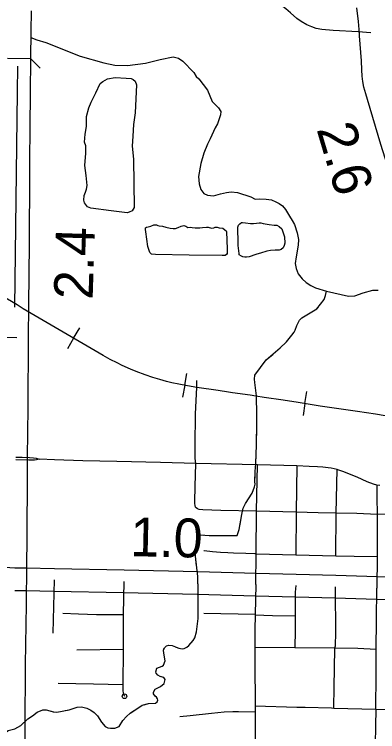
# Model space of a CAD drawing. Extents: x 1382482 to 1385815, y 1168351 to 1170484.
# Drawn here: x 1384330.9 to 1384488.7, y 1168998.2 to 1169309.6 of the extents above; entities that cross this region are included whole.
import ezdxf

# ---------------------------------------------------------------- set-up
doc = ezdxf.new("R2010")
doc.units = 0
for name, color, linetype in [('10', 7, 'Continuous'), ('15', 7, 'Continuous'), ('35', 7, 'Continuous'), ('37', 7, 'Continuous'), ('43', 7, 'Continuous'), ('48', 7, 'Continuous'), ('6', 7, 'Continuous'), ('Default', 7, 'Continuous')]:
    doc.layers.add(name, color=color, linetype=linetype)

msp = doc.modelspace()

# ---------------------------------------------------------------- linework, layer by layer
at = {"layer": '10'}
for points in [[(1384509.13, 1169190.46), (1384507.47, 1169195.39), (1384504.6, 1169205.01), (1384501.25, 1169216.69), (1384497.32, 1169230.02), (1384495.16, 1169236.73), (1384491.99, 1169247.25), (1384490.18, 1169253.06), (1384484.26, 1169272.62), (1384483.6, 1169275.15), (1384482.81, 1169278.01), (1384482.25, 1169280.48), (1384481.95, 1169282.86), (1384481.85, 1169285.5), (1384481.66, 1169289.5), (1384480.92, 1169300.27), (1384480.85, 1169301.27), (1384480.43, 1169306.53), (1384479.68, 1169312.48)], [(1384326.29, 1169069.61), (1384331.5, 1169069.24)], [(1384331.14, 1169069.25), (1384336.01, 1169069.25), (1384348.29, 1169069.04), (1384378.57, 1169068.37), (1384410.62, 1169067.66), (1384436, 1169067.05), (1384453.29, 1169066.56), (1384470.56, 1169066.07), (1384488.49, 1169065.52), (1384517.63, 1169064.98), (1384517.16, 1169063.79), (1384516.67, 1169061.78), (1384516.58, 1169059.48), (1384516.75, 1169057.84), (1384517.21, 1169056.31), (1384517.71, 1169054.98)], [(1384517.71, 1169054.98), (1384488.24, 1169055.52), (1384470.26, 1169056.07), (1384453.01, 1169056.56), (1384435.73, 1169057.05), (1384410.39, 1169057.66), (1384378.35, 1169058.38), (1384348.09, 1169059.04), (1384335.92, 1169059.25), (1384331.15, 1169059.25)]]:
    msp.add_lwpolyline(points, dxfattribs=at)
at = {"layer": '15'}
for points in [[(1384338.14, 1169311.22), (1384338.09, 1169302.22)], [(1384338.09, 1169302.22), (1384337.98, 1169290.5)], [(1384327.98, 1169290.6), (1384337.98, 1169290.5), (1384337.83, 1169275.41), (1384337.65, 1169260.77), (1384337.55, 1169245.45), (1384337.52, 1169235.24), (1384337.47, 1169229.12), (1384337.37, 1169221.35), (1384337.33, 1169210.14), (1384337.09, 1169183.38)], [(1384337.09, 1169183.38), (1384336.96, 1169169.15), (1384336.69, 1169138.8), (1384336.5, 1169117.39), (1384336.5, 1169116.16), (1384336.52, 1169109.18), (1384336.32, 1169082.79), (1384336.16, 1169069.54), (1384336.14, 1169064.2), (1384336.07, 1169059.56), (1384335.99, 1169053.34), (1384335.59, 1169027.3), (1384335.44, 1168999.6), (1384335.28, 1168986.96)]]:
    msp.add_lwpolyline(points, dxfattribs=at)
at = {"layer": '35'}
for points in [[(1384338.06, 1169299.6), (1384340.71, 1169298.59), (1384344.62, 1169297.45), (1384359.5, 1169291.52), (1384369.85, 1169288.51), (1384374.52, 1169287.63), (1384380.02, 1169287.47), (1384387.91, 1169288.44), (1384394.23, 1169290.04), (1384399.97, 1169291.12), (1384402.2, 1169290.62), (1384404.08, 1169289.23), (1384408.82, 1169284.35), (1384409.95, 1169282.6), (1384410.99, 1169281.69), (1384414.89, 1169276.72), (1384416.91, 1169271.73), (1384419.6, 1169269.11), (1384420.56, 1169267.44), (1384420.52, 1169265.95), (1384419.23, 1169262.13), (1384418.21, 1169260.35), (1384416.01, 1169255.62), (1384414.82, 1169253.2), (1384413.28, 1169249.34), (1384411.88, 1169244.82), (1384410.91, 1169239.23), (1384411.18, 1169236), (1384411.94, 1169233.58), (1384413.28, 1169231.91), (1384414.84, 1169231.11), (1384417.37, 1169230.89), (1384420.43, 1169231.65), (1384423.01, 1169232.34), (1384425.11, 1169232.56), (1384427.9, 1169232.24), (1384433.64, 1169230.41), (1384435.52, 1169229.39), (1384437.62, 1169229.49), (1384440.36, 1169229.44), (1384442.67, 1169229.06), (1384444.56, 1169228.26), (1384445.95, 1169227.45), (1384447.35, 1169226.43), (1384448.69, 1169224.92), (1384450.47, 1169221.95), (1384451.65, 1169220.14), (1384452.56, 1169218.4), (1384453.82, 1169214.81)], [(1384372.97, 1169224.31), (1384364.18, 1169225.44), (1384362.67, 1169226.1), (1384361.35, 1169227.8), (1384361.07, 1169228.94), (1384361.25, 1169231.02), (1384361.82, 1169232.44), (1384362.29, 1169233.76), (1384362.58, 1169235.27), (1384362.1, 1169239.71), (1384361.54, 1169243.96), (1384361.63, 1169245.85), (1384362.01, 1169249.26), (1384362.01, 1169252.47), (1384361.44, 1169254.08), (1384361.63, 1169257.57), (1384362.2, 1169260.97), (1384362.29, 1169265.32), (1384363.24, 1169269.01), (1384364.28, 1169271.46), (1384366.26, 1169275.62), (1384368.25, 1169279.59), (1384369.38, 1169280.54), (1384371.36, 1169281.67), (1384374.67, 1169282.24)], [(1384374.67, 1169282.24), (1384379.49, 1169281.95), (1384381.66, 1169281.77), (1384382.51, 1169281.39), (1384383.46, 1169280.63), (1384384.02, 1169279.02), (1384383.46, 1169266.83), (1384382.7, 1169261.83), (1384382.32, 1169256.72), (1384382.13, 1169252.38), (1384382.61, 1169246.8), (1384382.98, 1169225.73), (1384382.04, 1169224.31), (1384380.81, 1169223.74), (1384379.87, 1169223.46), (1384372.97, 1169224.31)], [(1384406.82, 1169205), (1384392.18, 1169205.29), (1384390.47, 1169205.52), (1384389.72, 1169206.23), (1384388.96, 1169208.83), (1384388.07, 1169215.21), (1384387.88, 1169216.2), (1384387.83, 1169216.96), (1384388.25, 1169217.24), (1384389.06, 1169217.34), (1384390.24, 1169217.62), (1384391.56, 1169218.23), (1384392.6, 1169218.23), (1384393.26, 1169217.95), (1384393.88, 1169217.81), (1384395.25, 1169217.72), (1384396.71, 1169217.29), (1384398.6, 1169216.72), (1384399.83, 1169216.58), (1384400.87, 1169216.63), (1384402.09, 1169217.01), (1384403.42, 1169217.62), (1384404.5, 1169217.9), (1384405.45, 1169217.72), (1384406.25, 1169217.01), (1384407.24, 1169217.2)], [(1384440.56, 1169206.82), (1384437.91, 1169205.97), (1384436.26, 1169205.5), (1384434.89, 1169205.03), (1384433.76, 1169204.65), (1384432.86, 1169204.27), (1384431.82, 1169204.13), (1384431.11, 1169204.13), (1384430.17, 1169204.37), (1384429.6, 1169204.7), (1384428.56, 1169205.26), (1384428.56, 1169205.83), (1384428.14, 1169209.23), (1384428.18, 1169212.54), (1384427.99, 1169214.81), (1384428.04, 1169217.17), (1384428.32, 1169218.16), (1384428.89, 1169218.73), (1384429.65, 1169219.2), (1384430.03, 1169219.2), (1384431.4, 1169219.16), (1384433.43, 1169218.78), (1384434.75, 1169218.87), (1384436.07, 1169219.01), (1384437.25, 1169219.11), (1384438.06, 1169219.11), (1384438.95, 1169218.78)], [(1384438.95, 1169218.78), (1384441.6, 1169218.4), (1384443.77, 1169218.16), (1384444.9, 1169218.02), (1384445.9, 1169217.5), (1384447.08, 1169216.46), (1384448.21, 1169213.06), (1384448.4, 1169210.23), (1384448.16, 1169209.28), (1384447.69, 1169208.19), (1384446.79, 1169207.58), (1384445.9, 1169207.25), (1384444.2, 1169207.2), (1384442.26, 1169207.15), (1384440.56, 1169206.82)], [(1384407.24, 1169217.2), (1384408.14, 1169217.01), (1384409.51, 1169216.91), (1384410.22, 1169216.96), (1384411.49, 1169216.96), (1384412.68, 1169217.01), (1384414.33, 1169217.15), (1384415.13, 1169217.15), (1384416.55, 1169216.82), (1384417.59, 1169216.91), (1384418.16, 1169217.2), (1384419.05, 1169217.2), (1384419.95, 1169216.96), (1384421.51, 1169216.72), (1384422.41, 1169216.06), (1384422.97, 1169215.68), (1384423.07, 1169215.21), (1384423.3, 1169207.79), (1384423.35, 1169205.76), (1384423.11, 1169205.34), (1384422.5, 1169204.86), (1384421.18, 1169204.86), (1384406.82, 1169205)], [(1384453.82, 1169214.81), (1384454.4, 1169211.86), (1384454.22, 1169209.46), (1384453.31, 1169204.35), (1384452.88, 1169201.39), (1384453.36, 1169199.24), (1384454.28, 1169196.98), (1384455.89, 1169194.83), (1384457.66, 1169193.16), (1384459.76, 1169191.93), (1384461.78, 1169190.94), (1384466.59, 1169189.48), (1384476.05, 1169187.22), (1384478.79, 1169187.4), (1384482.46, 1169188.76), (1384486.6, 1169189.87), (1384489.02, 1169189.87)]]:
    msp.add_lwpolyline(points, dxfattribs=at)
at = {"layer": '37'}
msp.add_lwpolyline([(1384337.98, 1169290.5), (1384342.18, 1169286.22)], dxfattribs=at)
at = {"layer": '43'}
for points in [[(1384409.66, 1169074.29), (1384409.53, 1169076.09), (1384409.9, 1169077.86), (1384410.29, 1169080.57), (1384410.55, 1169082.51), (1384410.85, 1169083.39), (1384411.72, 1169083.62), (1384415.49, 1169083.4), (1384424.5, 1169083.36), (1384427.66, 1169083.37), (1384428.64, 1169085.87), (1384429.8, 1169092.39), (1384430.32, 1169095.24), (1384431.39, 1169097.19), (1384434.25, 1169101.67), (1384435.31, 1169104.51), (1384435.56, 1169105.69), (1384435.45, 1169106.68), (1384435.53, 1169111.16), (1384435.75, 1169114.63), (1384436.12, 1169122.62), (1384436.19, 1169132.45), (1384436.27, 1169135.59), (1384436.04, 1169143.97), (1384435.32, 1169149.76), (1384435.18, 1169151.27), (1384435.43, 1169152.9), (1384437.8, 1169156.26), (1384440.3, 1169159.59), (1384446.44, 1169164.79), (1384449.1, 1169167.48), (1384451.44, 1169170.38), (1384452.41, 1169171.59), (1384452.85, 1169172.55), (1384453.64, 1169174.59), (1384454.77, 1169176.77), (1384455.77, 1169177.91), (1384458.72, 1169179.57), (1384462.38, 1169181.72), (1384465.53, 1169185.79), (1384466.07, 1169187.56), (1384466.59, 1169189.48)], [(1384465.8, 1169186.69), (1384466.07, 1169187.56), (1384466.59, 1169189.48)], [(1384452.28, 1169171.44), (1384452.41, 1169171.59), (1384452.85, 1169172.55), (1384453.64, 1169174.59), (1384454.77, 1169176.77), (1384455.77, 1169177.91), (1384458.72, 1169179.57), (1384462.38, 1169181.72), (1384462.87, 1169182.35)], [(1384443.14, 1169161.99), (1384446.44, 1169164.79), (1384448.96, 1169167.34)], [(1384437.77, 1169156.22), (1384437.8, 1169156.26), (1384440.3, 1169159.59), (1384443.14, 1169161.99)], [(1384436.26, 1169135.92), (1384436.04, 1169143.97), (1384435.32, 1169149.76), (1384435.18, 1169151.27), (1384435.24, 1169151.7)], [(1384435.76, 1169114.81), (1384436.12, 1169122.62), (1384436.18, 1169130.64)], [(1384430.28, 1169095.03), (1384430.32, 1169095.24), (1384431.39, 1169097.19), (1384434.25, 1169101.67), (1384435.31, 1169104.51), (1384435.56, 1169105.69), (1384435.45, 1169106.68), (1384435.5, 1169109.54)], [(1384418.54, 1169083.38), (1384424.5, 1169083.36), (1384427.66, 1169083.37), (1384428.64, 1169085.87), (1384429.35, 1169089.84)], [(1384410.1, 1169070.15), (1384409.66, 1169074.29), (1384409.53, 1169076.09), (1384409.9, 1169077.86), (1384410.29, 1169080.57), (1384410.55, 1169082.51), (1384410.85, 1169083.39), (1384411.72, 1169083.62), (1384413.26, 1169083.53)], [(1384347.95, 1169006.76), (1384349.38, 1169006.66), (1384354.72, 1169007.65), (1384358.18, 1169008.84), (1384360.13, 1169008.93), (1384362.37, 1169008.39), (1384364.17, 1169007.52), (1384365.65, 1169006.53), (1384367.09, 1169004.98), (1384368.78, 1169002.31), (1384370.39, 1169000.33), (1384371.47, 1168999.81), (1384372.63, 1168999.62), (1384374.62, 1168999.72), (1384376.45, 1169000.45), (1384378.07, 1169003.06), (1384379.69, 1169004.79), (1384381.19, 1169006.12), (1384383.18, 1169007.53), (1384386.39, 1169009.59), (1384389.14, 1169010.33), (1384392.21, 1169010.59), (1384393, 1169011.12), (1384393.28, 1169011.8), (1384393.15, 1169012.36), (1384392.67, 1169013.08), (1384392.07, 1169013.55), (1384391.35, 1169014.55), (1384391.38, 1169015.31), (1384392.09, 1169016.59), (1384394.4, 1169017.81), (1384395.98, 1169019.06), (1384396.49, 1169020.86), (1384395.81, 1169021.65), (1384394.21, 1169022.04), (1384393.17, 1169022.72), (1384392.57, 1169023.51), (1384392.4, 1169024.11), (1384392.87, 1169025.79), (1384395.14, 1169026.65), (1384395.73, 1169027.09), (1384396.4, 1169028.86), (1384395.78, 1169032.29), (1384395.73, 1169033.61), (1384396.08, 1169034.61), (1384396.95, 1169035.46), (1384398.07, 1169035.78), (1384399.51, 1169035.55), (1384402.38, 1169034.34), (1384403.74, 1169034.15), (1384404.74, 1169034.27), (1384405.85, 1169034.84), (1384406.76, 1169035.61), (1384408.62, 1169037.78), (1384409.29, 1169038.94), (1384410.07, 1169041.55), (1384410.79, 1169047.27), (1384410.81, 1169050.91), (1384410.75, 1169059.5), (1384410.6, 1169065.46), (1384409.66, 1169074.29)], [(1384410.77, 1169056.98), (1384410.75, 1169059.5), (1384410.61, 1169064.9)], [(1384410.8, 1169049.06), (1384410.81, 1169050.91), (1384410.77, 1169056.98)], [(1384400.7, 1169035.05), (1384402.38, 1169034.34), (1384403.74, 1169034.15), (1384404.74, 1169034.27), (1384405.85, 1169034.84), (1384406.76, 1169035.61), (1384408.62, 1169037.78), (1384409.29, 1169038.94), (1384410.07, 1169041.55), (1384410.36, 1169043.81)], [(1384394.66, 1169021.93), (1384394.21, 1169022.04), (1384393.17, 1169022.72), (1384392.57, 1169023.51), (1384392.4, 1169024.11), (1384392.87, 1169025.79), (1384395.14, 1169026.65), (1384395.73, 1169027.09), (1384396.4, 1169028.86), (1384395.78, 1169032.29), (1384395.73, 1169033.61), (1384396.03, 1169034.47)], [(1384387.24, 1169009.82), (1384389.14, 1169010.33), (1384392.21, 1169010.59), (1384393, 1169011.12), (1384393.28, 1169011.8), (1384393.15, 1169012.36), (1384392.67, 1169013.08), (1384392.07, 1169013.55), (1384391.35, 1169014.55), (1384391.38, 1169015.31), (1384392.09, 1169016.59), (1384394.4, 1169017.81), (1384395.06, 1169018.33)], [(1384352.95, 1169007.32), (1384354.72, 1169007.65), (1384358.18, 1169008.84), (1384360.13, 1169008.93), (1384362.37, 1169008.39), (1384364.17, 1169007.52), (1384365.65, 1169006.53), (1384367.09, 1169004.98), (1384367.22, 1169004.78)], [(1384326.28, 1168997.1), (1384328.15, 1168998.67), (1384331.13, 1168999.45), (1384333.75, 1169000.79), (1384336.76, 1169003.69), (1384338.83, 1169004.98), (1384340.85, 1169006.6), (1384343.28, 1169007.57), (1384344.79, 1169007.7), (1384347.95, 1169006.76)], [(1384335.45, 1169002.43), (1384336.76, 1169003.69), (1384338.83, 1169004.98), (1384340.3, 1169006.16)], [(1384340.3, 1169006.16), (1384340.85, 1169006.6), (1384343.28, 1169007.57), (1384344.79, 1169007.7), (1384347.75, 1169006.82)], [(1384370.26, 1169000.48), (1384370.39, 1169000.33), (1384371.47, 1168999.81), (1384372.63, 1168999.62), (1384374.62, 1168999.72), (1384376.45, 1169000.45), (1384378.07, 1169003.06), (1384379.69, 1169004.79), (1384381.19, 1169006.12), (1384382.7, 1169007.19)]]:
    msp.add_lwpolyline(points, dxfattribs=at)
at = {"layer": '6'}
msp.add_lwpolyline([(1384332.27, 1169287.07), (1384332.16, 1169275.88), (1384331.01, 1169182.44)], dxfattribs=at)
at = {"layer": 'Default'}
for p, q in [((1384356.63, 1169168.97), (1384359.3, 1169173.53)), ((1384356.63, 1169168.97), (1384353.96, 1169164.42)), ((1384404.93, 1169148.55), (1384405.85, 1169153.75)), ((1384404.93, 1169148.55), (1384404, 1169143.35)), ((1384457.12, 1169140.59), (1384457.92, 1169145.8)), ((1384457.12, 1169140.59), (1384456.32, 1169135.37))]:
    msp.add_line(p, q, dxfattribs=at)
for points in [[(1384485.83, 1169301.65), (1384480.21, 1169302.01), (1384469.44, 1169302.66), (1384464.54, 1169303.11), (1384461.99, 1169303.55), (1384460.17, 1169304.2), (1384457.91, 1169305.13), (1384455.48, 1169306.51), (1384453.7, 1169307.76), (1384450.88, 1169310.27), (1384448.86, 1169312.05), (1384446.1, 1169314.24), (1384444.28, 1169315.54), (1384443.03, 1169316.51)], [(1384410.16, 1169147.67), (1384406.14, 1169148.34), (1384402.36, 1169149.01), (1384399.38, 1169149.68), (1384397.01, 1169150.25), (1384394.16, 1169151.05), (1384391.14, 1169151.93), (1384387.74, 1169153.08), (1384383.77, 1169154.53), (1384381.34, 1169155.53), (1384377.78, 1169157.17), (1384375.53, 1169158.27), (1384372.49, 1169159.79), (1384369.42, 1169161.46), (1384359.04, 1169167.56), (1384334.76, 1169181.81), (1384332.09, 1169183.43), (1384316.13, 1169192.72)], [(1384487.82, 1169135.95), (1384480.03, 1169137.11), (1384463.76, 1169139.56), (1384454.15, 1169141.04), (1384447.76, 1169142.05), (1384439.37, 1169143.27), (1384435.78, 1169143.84), (1384433.31, 1169144.22), (1384425.71, 1169145.35), (1384423.96, 1169145.57), (1384419.5, 1169146.26), (1384410.16, 1169147.67), (1384406.14, 1169148.34), (1384402.36, 1169149.01), (1384399.38, 1169149.68), (1384397.01, 1169150.25), (1384394.16, 1169151.05), (1384391.14, 1169151.93), (1384387.74, 1169153.08), (1384383.77, 1169154.53), (1384381.34, 1169155.53), (1384377.78, 1169157.17), (1384375.53, 1169158.27), (1384372.49, 1169159.79), (1384369.42, 1169161.46), (1384359.04, 1169167.56), (1384334.76, 1169181.81), (1384332.09, 1169183.43), (1384316.13, 1169192.72)], [(1384331.96, 1169169.19), (1384314.28, 1169169.67), (1384277.37, 1169170.33), (1384272.78, 1169170.37), (1384262.71, 1169170.66), (1384249.71, 1169170.88), (1384242.27, 1169170.99), (1384240.25, 1169170.88), (1384238.46, 1169170.55), (1384236.74, 1169170.18), (1384235.79, 1169169.85), (1384232.67, 1169168.97), (1384229.38, 1169167.88), (1384227.8, 1169167.25), (1384226.45, 1169166.81)], [(1384409.69, 1169114.58), (1384409.52, 1169116.76), (1384409.52, 1169122.33), (1384409.64, 1169136.22), (1384410.16, 1169147.67), (1384410.22, 1169150.67)], [(1384496.19, 1169134.6), (1384487.82, 1169135.95), (1384480.03, 1169137.11), (1384463.76, 1169139.56), (1384454.15, 1169141.04), (1384447.76, 1169142.05), (1384439.37, 1169143.27), (1384435.78, 1169143.84), (1384433.31, 1169144.22), (1384425.71, 1169145.35), (1384423.96, 1169145.57), (1384419.5, 1169146.26), (1384410.16, 1169147.67)], [(1384496.19, 1169134.6), (1384487.82, 1169135.95)], [(1384331.5, 1169117.41), (1384334.23, 1169117.37), (1384337.52, 1169117.25), (1384339.29, 1169117.11), (1384340.4, 1169116.85), (1384341.73, 1169116.52)], [(1384341.84, 1169116.48), (1384340.55, 1169116.18), (1384339.62, 1169116.07), (1384337.26, 1169116.11), (1384331.5, 1169116.15)], [(1384489.75, 1169105.07), (1384488.38, 1169105.21), (1384487.01, 1169105.64), (1384484.17, 1169106.63), (1384479.89, 1169108.63), (1384473.64, 1169111.14), (1384471.45, 1169111.82), (1384471.13, 1169111.94), (1384468.53, 1169112.53), (1384467.2, 1169112.67), (1384464.98, 1169112.97), (1384462.66, 1169113.19), (1384459, 1169113.3), (1384453.65, 1169113.52), (1384436.49, 1169113.98), (1384409.69, 1169114.58), (1384394.35, 1169115), (1384375.49, 1169115.44), (1384360.7, 1169115.78), (1384348.33, 1169116.26), (1384341.84, 1169116.48)], [(1384525.92, 1169092.85), (1384515.55, 1169092.72), (1384507.41, 1169092.74), (1384501.76, 1169092.67), (1384498.36, 1169092.71), (1384496.44, 1169092.56), (1384494.7, 1169092.56), (1384488.59, 1169092.52), (1384479.65, 1169092.89), (1384470.75, 1169093.07), (1384462.87, 1169093.22), (1384453.41, 1169093.52), (1384436.05, 1169093.87), (1384420.57, 1169094.22), (1384412.83, 1169094.44), (1384411.24, 1169094.63), (1384410.47, 1169094.96), (1384409.95, 1169095.29), (1384409.66, 1169095.7), (1384409.43, 1169096.4), (1384409.32, 1169097.18), (1384409.32, 1169098.1), (1384409.51, 1169104.64), (1384409.69, 1169114.58)], [(1384435.86, 1169062.05), (1384435.9, 1169075.38), (1384435.89, 1169075.55), (1384436.05, 1169093.87), (1384436.49, 1169113.98)], [(1384453.65, 1169113.52), (1384453.41, 1169093.52), (1384453.14, 1169075)], [(1384470.75, 1169093.07), (1384471.13, 1169111.94)], [(1384488.38, 1169105.21), (1384488.43, 1169099.97), (1384488.59, 1169092.52), (1384488.46, 1169074.25), (1384488.37, 1169060.52)], [(1384470.6, 1169074.52), (1384470.75, 1169093.07)], [(1384413.27, 1169076.83), (1384413.31, 1169076.83), (1384417.05, 1169076.4), (1384420.52, 1169076.16), (1384423.71, 1169075.92), (1384426.14, 1169075.85), (1384431.54, 1169075.7), (1384435.34, 1169075.58), (1384435.89, 1169075.55)], [(1384435.9, 1169075.38), (1384453.14, 1169075), (1384470.6, 1169074.52), (1384478.54, 1169074.31), (1384488.46, 1169074.25)], [(1384348.19, 1169064.04), (1384347.66, 1169040.94)], [(1384378.46, 1169063.38), (1384378.25, 1169049.07), (1384378.17, 1169033.83), (1384377.99, 1169018.49), (1384378.09, 1169015.93), (1384378.23, 1169015.05), (1384378.41, 1169014.17), (1384378.74, 1169013.52)], [(1384435.86, 1169062.05), (1384435.54, 1169049.02), (1384435.55, 1169048.88), (1384435.42, 1169042.34), (1384435.45, 1169034.88), (1384435.38, 1169028.44), (1384435.52, 1169009.23), (1384435.47, 1169006.8), (1384435.47, 1168994.91)], [(1384453.15, 1169061.56), (1384452.92, 1169058.8), (1384452.96, 1169053.53), (1384452.85, 1169048.4), (1384452.92, 1169042.14), (1384452.77, 1169034.73)], [(1384469.71, 1169008.24), (1384469.78, 1169017.72), (1384470.03, 1169025.42), (1384470.17, 1169034.62), (1384470.38, 1169035.36), (1384470.49, 1169036.77), (1384470.52, 1169039.92), (1384470.41, 1169061.07)], [(1384487.98, 1169007.85), (1384488.16, 1169023.15), (1384488.07, 1169034.04), (1384488.29, 1169046.62), (1384488.37, 1169060.52)], [(1384351.92, 1169049.54), (1384358.79, 1169049.26), (1384366.59, 1169048.98), (1384378.25, 1169049.07)], [(1384435.54, 1169049.02), (1384413.26, 1169049.45)], [(1384435.55, 1169048.88), (1384443, 1169048.64), (1384452.85, 1169048.4)], [(1384378.17, 1169033.83), (1384358.01, 1169033.6)], [(1384435.45, 1169034.88), (1384452.77, 1169034.73), (1384470.17, 1169034.62), (1384480.15, 1169034.36), (1384488.07, 1169034.04)], [(1384377.99, 1169018.49), (1384365.27, 1169018.81), (1384349.89, 1169019.05)], [(1384536.15, 1169006.66), (1384514.78, 1169007.11), (1384506.53, 1169007.4), (1384487.98, 1169007.85), (1384469.71, 1169008.24), (1384468.76, 1169008.33), (1384457.28, 1169008.63), (1384453.61, 1169008.63), (1384435.52, 1169009.23)], [(1384402.77, 1169004.74), (1384407.27, 1169005.21), (1384416.52, 1169006.17), (1384422.08, 1169006.79), (1384425.85, 1169006.93), (1384428.23, 1169006.93), (1384435.47, 1169006.8)], [(1384487.98, 1169007.85), (1384487.83, 1169000.68), (1384487.67, 1168992.54)]]:
    msp.add_lwpolyline(points, dxfattribs=at)
msp.add_circle((1384378.74, 1169013.52), 1, dxfattribs=at)

# ---------------------------------------------------------------- texts
at = {"layer": '48'}
for s, rotation, p in [('2.6', 286.5932, (1384462.11, 1169259.86)), ('2.4', 88.153, (1384364.9, 1169185.61)), ('1.0', 358.7266, (1384381.11, 1169074.39))]:
    msp.add_text(s, height=16.896, rotation=rotation, dxfattribs=at).set_placement(p)

doc.saveas('drawing.dxf')
